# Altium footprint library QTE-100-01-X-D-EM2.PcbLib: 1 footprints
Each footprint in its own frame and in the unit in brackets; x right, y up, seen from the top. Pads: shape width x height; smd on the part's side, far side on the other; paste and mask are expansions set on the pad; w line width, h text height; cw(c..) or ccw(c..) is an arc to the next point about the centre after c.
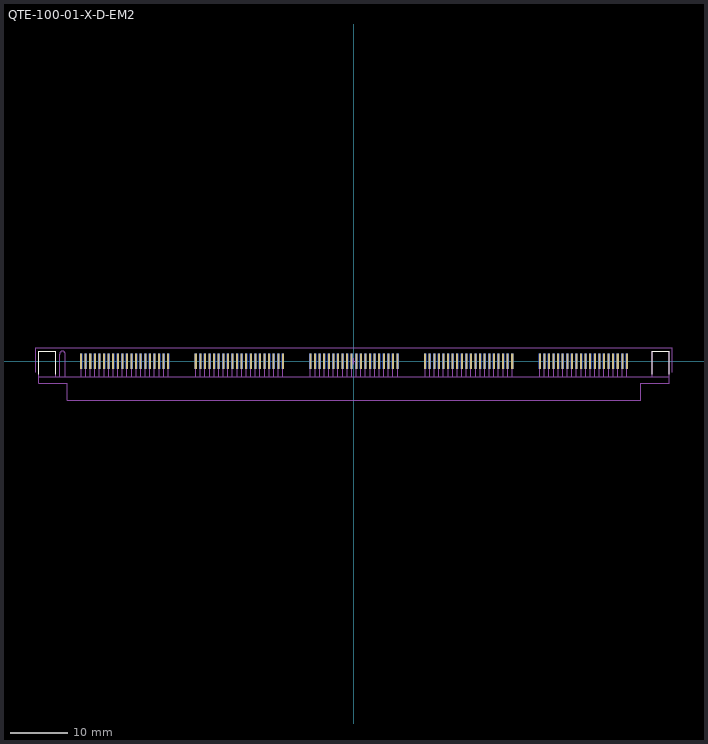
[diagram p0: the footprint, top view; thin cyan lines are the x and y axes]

## QTE-100-01-X-D-EM2 [mm] "0.80mm pitch, 200 pin, high speed terminal strip; w/edge mounts"
height 2.99
pads (200):
  rect 0.35x2.65 smd mask+0: 1(-47.606,0) 3(-46.806,0) 5(-46.006,0) 7(-45.206,0) 9(-44.406,0) 11(-43.606,0) 13(-42.806,0) 15(-42.006,0) 17(-41.206,0) 19(-40.406,0) 21(-39.606,0) 23(-38.806,0) 25(-38.006,0) 27(-37.206,0) 29(-36.406,0) 31(-35.606,0) 33(-34.806,0) 35(-34.006,0) 37(-33.206,0) 39(-32.406,0) 41(-27.603,0) 43(-26.803,0) 45(-26.003,0) 47(-25.203,0) 49(-24.403,0) 51(-23.603,0) 53(-22.803,0) 55(-22.003,0) 57(-21.203,0) 59(-20.403,0) 61(-19.603,0) 63(-18.803,0) 65(-18.003,0) 67(-17.203,0) 69(-16.403,0) 71(-15.603,0) 73(-14.803,0) 75(-14.003,0) 77(-13.203,0) 79(-12.403,0) 81(-7.6,0) 83(-6.8,0) 85(-6,0) 87(-5.2,0) 89(-4.4,0) 91(-3.6,0) 93(-2.8,0) 95(-2,0) 97(-1.2,0) 99(-0.4,0) 101(0.4,0) 103(1.2,0) 105(2,0) 107(2.8,0) 109(3.6,0) 111(4.4,0) 113(5.2,0) 115(6,0) 117(6.8,0) 119(7.6,0) 121(12.403,0) 123(13.203,0) 125(14.003,0) 127(14.803,0) 129(15.603,0) 131(16.403,0) 133(17.203,0) 135(18.003,0) 137(18.803,0) 139(19.603,0) 141(20.403,0) 143(21.203,0) 145(22.003,0) 147(22.803,0) 149(23.603,0) 151(24.403,0) 153(25.203,0) 155(26.003,0) 157(26.803,0) 159(27.603,0) 161(32.406,0) 163(33.206,0) 165(34.006,0) 167(34.806,0) 169(35.606,0) 171(36.406,0) 173(37.206,0) 175(38.006,0) 177(38.806,0) 179(39.606,0) 181(40.406,0) 183(41.206,0) 185(42.006,0) 187(42.806,0) 189(43.606,0) 191(44.406,0) 193(45.206,0) 195(46.006,0) 197(46.806,0) 199(47.606,0)
  rect 0.35x2.65 smd far side mask+0: 2(-47.606,0) 4(-46.806,0) 6(-46.006,0) 8(-45.206,0) 10(-44.406,0) 12(-43.606,0) 14(-42.806,0) 16(-42.006,0) 18(-41.206,0) 20(-40.406,0) 22(-39.606,0) 24(-38.806,0) 26(-38.006,0) 28(-37.206,0) 30(-36.406,0) 32(-35.606,0) 34(-34.806,0) 36(-34.006,0) 38(-33.206,0) 40(-32.406,0) 42(-27.603,0) 44(-26.803,0) 46(-26.003,0) 48(-25.203,0) 50(-24.403,0) 52(-23.603,0) 54(-22.803,0) 56(-22.003,0) 58(-21.203,0) 60(-20.403,0) 62(-19.603,0) 64(-18.803,0) 66(-18.003,0) 68(-17.203,0) 70(-16.403,0) 72(-15.603,0) 74(-14.803,0) 76(-14.003,0) 78(-13.203,0) 80(-12.403,0) 82(-7.6,0) 84(-6.8,0) 86(-6,0) 88(-5.2,0) 90(-4.4,0) 92(-3.6,0) 94(-2.8,0) 96(-2,0) 98(-1.2,0) 100(-0.4,0) 102(0.4,0) 104(1.2,0) 106(2,0) 108(2.8,0) 110(3.6,0) 112(4.4,0) 114(5.2,0) 116(6,0) 118(6.8,0) 120(7.6,0) 122(12.403,0) 124(13.203,0) 126(14.003,0) 128(14.803,0) 130(15.603,0) 132(16.403,0) 134(17.203,0) 136(18.003,0) 138(18.803,0) 140(19.603,0) 142(20.403,0) 144(21.203,0) 146(22.003,0) 148(22.803,0) 150(23.603,0) 152(24.403,0) 154(25.203,0) 156(26.003,0) 158(26.803,0) 160(27.603,0) 162(32.406,0) 164(33.206,0) 166(34.006,0) 168(34.806,0) 170(35.606,0) 172(36.406,0) 174(37.206,0) 176(38.006,0) 178(38.806,0) 180(39.606,0) 182(40.406,0) 184(41.206,0) 186(42.006,0) 188(42.806,0) 190(43.606,0) 192(44.406,0) 194(45.206,0) 196(46.006,0) 198(46.806,0) 200(47.606,0)
Top Overlay:
  lines w0.2: -55,-2.3 -55,1.7 -52,1.7 -52,-2.3 ; 52,-2.3 52,1.7 55,1.7 55,-2.3
Top Solder:
  lines w0.127: -47.606,0 -47.606,1.333 ; -46.806,0 -46.806,1.333 ; -46.006,0 -46.006,1.333 ; -45.206,0 -45.206,1.333 ; -44.406,0 -44.406,1.333 ; -43.606,0 -43.606,1.333 ; -42.806,0 -42.806,1.333 ; -42.006,0 -42.006,1.333 ; -41.206,0 -41.206,1.333 ; -40.406,0 -40.406,1.333 ; -39.606,0 -39.606,1.333 ; -38.806,0 -38.806,1.333 ; -38.006,0 -38.006,1.333 ; -37.206,0 -37.206,1.333 ; -36.406,0 -36.406,1.333 ; -35.606,0 -35.606,1.333 ; -34.806,0 -34.806,1.333 ; -34.006,0 -34.006,1.333 ; -33.206,0 -33.206,1.333 ; -32.406,0 -32.406,1.333 ; -27.603,0 -27.603,1.333 ; -26.803,0 -26.803,1.333 ; -26.003,0 -26.003,1.333 ; -25.203,0 -25.203,1.333 ; -24.403,0 -24.403,1.333 ; -23.603,0 -23.603,1.333 ; -22.803,0 -22.803,1.333 ; -22.003,0 -22.003,1.333 ; -21.203,0 -21.203,1.333 ; -20.403,0 -20.403,1.333 ; -19.603,0 -19.603,1.333 ; -18.803,0 -18.803,1.333 ; -18.003,0 -18.003,1.333 ; -17.203,0 -17.203,1.333 ; -16.403,0 -16.403,1.333 ; -15.603,0 -15.603,1.333 ; -14.803,0 -14.803,1.333 ; -14.003,0 -14.003,1.333 ; -13.203,0 -13.203,1.333 ; -12.403,0 -12.403,1.333 ; -7.6,0 -7.6,1.333 ; -6.8,0 -6.8,1.333 ; -6,0 -6,1.333 ; -5.2,0 -5.2,1.333 ; -4.4,0 -4.4,1.333 ; -3.6,0 -3.6,1.333 ; -2.8,0 -2.8,1.333 ; -2,0 -2,1.333 ; -1.2,0 -1.2,1.333 ; -0.4,0 -0.4,1.333 ; 0.4,0 0.4,1.333 ; 1.2,0 1.2,1.333 ; 2,0 2,1.333 ; 2.8,0 2.8,1.333 ; 3.6,0 3.6,1.333 ; 4.4,0 4.4,1.333 ; 5.2,0 5.2,1.333 ; 6,0 6,1.333 ; 6.8,0 6.8,1.333 ; 7.6,0 7.6,1.333 ; 12.403,0 12.403,1.333 ; 13.203,0 13.203,1.333 ; 14.003,0 14.003,1.333 ; 14.803,0 14.803,1.333 ; 15.603,0 15.603,1.333 ; 16.403,0 16.403,1.333 ; 17.203,0 17.203,1.333 ; 18.003,0 18.003,1.333 ; 18.803,0 18.803,1.333 ; 19.603,0 19.603,1.333 ; 20.403,0 20.403,1.333 ; 21.203,0 21.203,1.333 ; 22.003,0 22.003,1.333 ; 22.803,0 22.803,1.333 ; 23.603,0 23.603,1.333 ; 24.403,0 24.403,1.333 ; 25.203,0 25.203,1.333 ; 26.003,0 26.003,1.333 ; 26.803,0 26.803,1.333 ; 27.603,0 27.603,1.333 ; 32.406,0 32.406,1.333 ; 33.206,0 33.206,1.333 ; 34.006,0 34.006,1.333 ; 34.806,0 34.806,1.333 ; 35.606,0 35.606,1.333 ; 36.406,0 36.406,1.333 ; 37.206,0 37.206,1.333 ; 38.006,0 38.006,1.333 ; 38.806,0 38.806,1.333 ; 39.606,0 39.606,1.333 ; 40.406,0 40.406,1.333 ; 41.206,0 41.206,1.333 ; 42.006,0 42.006,1.333 ; 42.806,0 42.806,1.333 ; 43.606,0 43.606,1.333 ; 44.406,0 44.406,1.333 ; 45.206,0 45.206,1.333 ; 46.006,0 46.006,1.333 ; 46.806,0 46.806,1.333 ; 47.606,0 47.606,1.333
Bottom Solder:
  lines w0.127: -47.606,0 -47.606,1.333 ; -46.806,0 -46.806,1.333 ; -46.006,0 -46.006,1.333 ; -45.206,0 -45.206,1.333 ; -44.406,0 -44.406,1.333 ; -43.606,0 -43.606,1.333 ; -42.806,0 -42.806,1.333 ; -42.006,0 -42.006,1.333 ; -41.206,0 -41.206,1.333 ; -40.406,0 -40.406,1.333 ; -39.606,0 -39.606,1.333 ; -38.806,0 -38.806,1.333 ; -38.006,0 -38.006,1.333 ; -37.206,0 -37.206,1.333 ; -36.406,0 -36.406,1.333 ; -35.606,0 -35.606,1.333 ; -34.806,0 -34.806,1.333 ; -34.006,0 -34.006,1.333 ; -33.206,0 -33.206,1.333 ; -32.406,0 -32.406,1.333 ; -27.603,0 -27.603,1.333 ; -26.803,0 -26.803,1.333 ; -26.003,0 -26.003,1.333 ; -25.203,0 -25.203,1.333 ; -24.403,0 -24.403,1.333 ; -23.603,0 -23.603,1.333 ; -22.803,0 -22.803,1.333 ; -22.003,0 -22.003,1.333 ; -21.203,0 -21.203,1.333 ; -20.403,0 -20.403,1.333 ; -19.603,0 -19.603,1.333 ; -18.803,0 -18.803,1.333 ; -18.003,0 -18.003,1.333 ; -17.203,0 -17.203,1.333 ; -16.403,0 -16.403,1.333 ; -15.603,0 -15.603,1.333 ; -14.803,0 -14.803,1.333 ; -14.003,0 -14.003,1.333 ; -13.203,0 -13.203,1.333 ; -12.403,0 -12.403,1.333 ; -7.6,0 -7.6,1.333 ; -6.8,0 -6.8,1.333 ; -6,0 -6,1.333 ; -5.2,0 -5.2,1.333 ; -4.4,0 -4.4,1.333 ; -3.6,0 -3.6,1.333 ; -2.8,0 -2.8,1.333 ; -2,0 -2,1.333 ; -1.2,0 -1.2,1.333 ; -0.4,0 -0.4,1.333 ; 0.4,0 0.4,1.333 ; 1.2,0 1.2,1.333 ; 2,0 2,1.333 ; 2.8,0 2.8,1.333 ; 3.6,0 3.6,1.333 ; 4.4,0 4.4,1.333 ; 5.2,0 5.2,1.333 ; 6,0 6,1.333 ; 6.8,0 6.8,1.333 ; 7.6,0 7.6,1.333 ; 12.403,0 12.403,1.333 ; 13.203,0 13.203,1.333 ; 14.003,0 14.003,1.333 ; 14.803,0 14.803,1.333 ; 15.603,0 15.603,1.333 ; 16.403,0 16.403,1.333 ; 17.203,0 17.203,1.333 ; 18.003,0 18.003,1.333 ; 18.803,0 18.803,1.333 ; 19.603,0 19.603,1.333 ; 20.403,0 20.403,1.333 ; 21.203,0 21.203,1.333 ; 22.003,0 22.003,1.333 ; 22.803,0 22.803,1.333 ; 23.603,0 23.603,1.333 ; 24.403,0 24.403,1.333 ; 25.203,0 25.203,1.333 ; 26.003,0 26.003,1.333 ; 26.803,0 26.803,1.333 ; 27.603,0 27.603,1.333 ; 32.406,0 32.406,1.333 ; 33.206,0 33.206,1.333 ; 34.006,0 34.006,1.333 ; 34.806,0 34.806,1.333 ; 35.606,0 35.606,1.333 ; 36.406,0 36.406,1.333 ; 37.206,0 37.206,1.333 ; 38.006,0 38.006,1.333 ; 38.806,0 38.806,1.333 ; 39.606,0 39.606,1.333 ; 40.406,0 40.406,1.333 ; 41.206,0 41.206,1.333 ; 42.006,0 42.006,1.333 ; 42.806,0 42.806,1.333 ; 43.606,0 43.606,1.333 ; 44.406,0 44.406,1.333 ; 45.206,0 45.206,1.333 ; 46.006,0 46.006,1.333 ; 46.806,0 46.806,1.333 ; 47.606,0 47.606,1.333
Mechanical 13:
  lines w0.1: -52,-2.73 -52,1.7 -55,1.7 -55,-2.73 ; -51.35,-2.73 -51.35,1.242 cw(c-50.85,1.242) -50.35,1.242 -50.35,-2.73 ; -47.606,-2.73 -47.606,0 ; -46.806,-2.73 -46.806,0 ; -46.006,-2.73 -46.006,0 ; -45.206,-2.73 -45.206,0 ; -44.406,-2.73 -44.406,0 ; -43.606,-2.73 -43.606,0 ; -42.806,-2.73 -42.806,0 ; -42.006,-2.73 -42.006,0 ; -41.206,-2.73 -41.206,0 ; -40.406,-2.73 -40.406,0 ; -39.606,-2.73 -39.606,0 ; -38.806,-2.73 -38.806,0 ; -38.006,-2.73 -38.006,0 ; -37.206,-2.73 -37.206,0 ; -36.406,-2.73 -36.406,0 ; -35.606,-2.73 -35.606,0 ; -34.806,-2.73 -34.806,0 ; -34.006,-2.73 -34.006,0 ; -33.206,-2.73 -33.206,0 ; -32.406,-2.73 -32.406,0 ; -27.603,-2.73 -27.603,0 ; -26.803,-2.73 -26.803,0 ; -26.003,-2.73 -26.003,0 ; -25.203,-2.73 -25.203,0 ; -24.403,-2.73 -24.403,0 ; -23.603,-2.73 -23.603,0 ; -22.803,-2.73 -22.803,0 ; -22.003,-2.73 -22.003,0 ; -21.203,-2.73 -21.203,0 ; -20.403,-2.73 -20.403,0 ; -19.603,-2.73 -19.603,0 ; -18.803,-2.73 -18.803,0 ; -18.003,-2.73 -18.003,0 ; -17.203,-2.73 -17.203,0 ; -16.403,-2.73 -16.403,0 ; -15.603,-2.73 -15.603,0 ; -14.803,-2.73 -14.803,0 ; -14.003,-2.73 -14.003,0 ; -13.203,-2.73 -13.203,0 ; -12.403,-2.73 -12.403,0 ; -7.6,-2.73 -7.6,0 ; -6.8,-2.73 -6.8,0 ; -6,-2.73 -6,0 ; -5.2,-2.73 -5.2,0 ; -4.4,-2.73 -4.4,0 ; -3.6,-2.73 -3.6,0 ; -2.8,-2.73 -2.8,0 ; -2,-2.73 -2,0 ; -1.2,-2.73 -1.2,0 ; -0.4,-2.73 -0.4,0 ; 0.4,-2.73 0.4,0 ; 1.2,-2.73 1.2,0 ; 2,-2.73 2,0 ; 2.8,-2.73 2.8,0 ; 3.6,-2.73 3.6,0 ; 4.4,-2.73 4.4,0 ; 5.2,-2.73 5.2,0 ; 6,-2.73 6,0 ; 6.8,-2.73 6.8,0 ; 7.6,-2.73 7.6,0 ; 12.403,-2.73 12.403,0 ; 13.203,-2.73 13.203,0 ; 14.003,-2.73 14.003,0 ; 14.803,-2.73 14.803,0 ; 15.603,-2.73 15.603,0 ; 16.403,-2.73 16.403,0 ; 17.203,-2.73 17.203,0 ; 18.003,-2.73 18.003,0 ; 18.803,-2.73 18.803,0 ; 19.603,-2.73 19.603,0 ; 20.403,-2.73 20.403,0 ; 21.203,-2.73 21.203,0 ; 22.003,-2.73 22.003,0 ; 22.803,-2.73 22.803,0 ; 23.603,-2.73 23.603,0 ; 24.403,-2.73 24.403,0 ; 25.203,-2.73 25.203,0 ; 26.003,-2.73 26.003,0 ; 26.803,-2.73 26.803,0 ; 27.603,-2.73 27.603,0 ; 32.406,-2.73 32.406,0 ; 33.206,-2.73 33.206,0 ; 34.006,-2.73 34.006,0 ; 34.806,-2.73 34.806,0 ; 35.606,-2.73 35.606,0 ; 36.406,-2.73 36.406,0 ; 37.206,-2.73 37.206,0 ; 38.006,-2.73 38.006,0 ; 38.806,-2.73 38.806,0 ; 39.606,-2.73 39.606,0 ; 40.406,-2.73 40.406,0 ; 41.206,-2.73 41.206,0 ; 42.006,-2.73 42.006,0 ; 42.806,-2.73 42.806,0 ; 43.606,-2.73 43.606,0 ; 44.406,-2.73 44.406,0 ; 45.206,-2.73 45.206,0 ; 46.006,-2.73 46.006,0 ; 46.806,-2.73 46.806,0 ; 47.606,-2.73 47.606,0 ; 52,-2.73 52,1.7 55,1.7 55,-2.73 ; -55,-2.73 -55,-3.85 -50,-3.85 -50,-6.8 50.05,-6.8 50.05,-3.85 55,-3.85 55,-2.73 ; -55,-2.73 55,-2.73
  text ".Designator" at 0,0 h1.52
Mechanical 15:
  lines w0.05: -55.5,-1.895 -55.5,2.35 55.5,2.35 55.5,-1.895 ; -0.5,0 0.5,0 ; 0,-0.5 0,0.5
